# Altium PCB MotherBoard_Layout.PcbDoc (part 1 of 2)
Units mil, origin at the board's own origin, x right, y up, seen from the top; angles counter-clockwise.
Board outline 5200 x 4470 mil, 4 copper layers (Top Layer, Int1 (GND), Int2 (PWR), Bottom Layer), stack 53.912 mil thick; 91 components, 57 nets, 316 pads, 326 vias.
Unrouted connection lines stored in the file: 3.
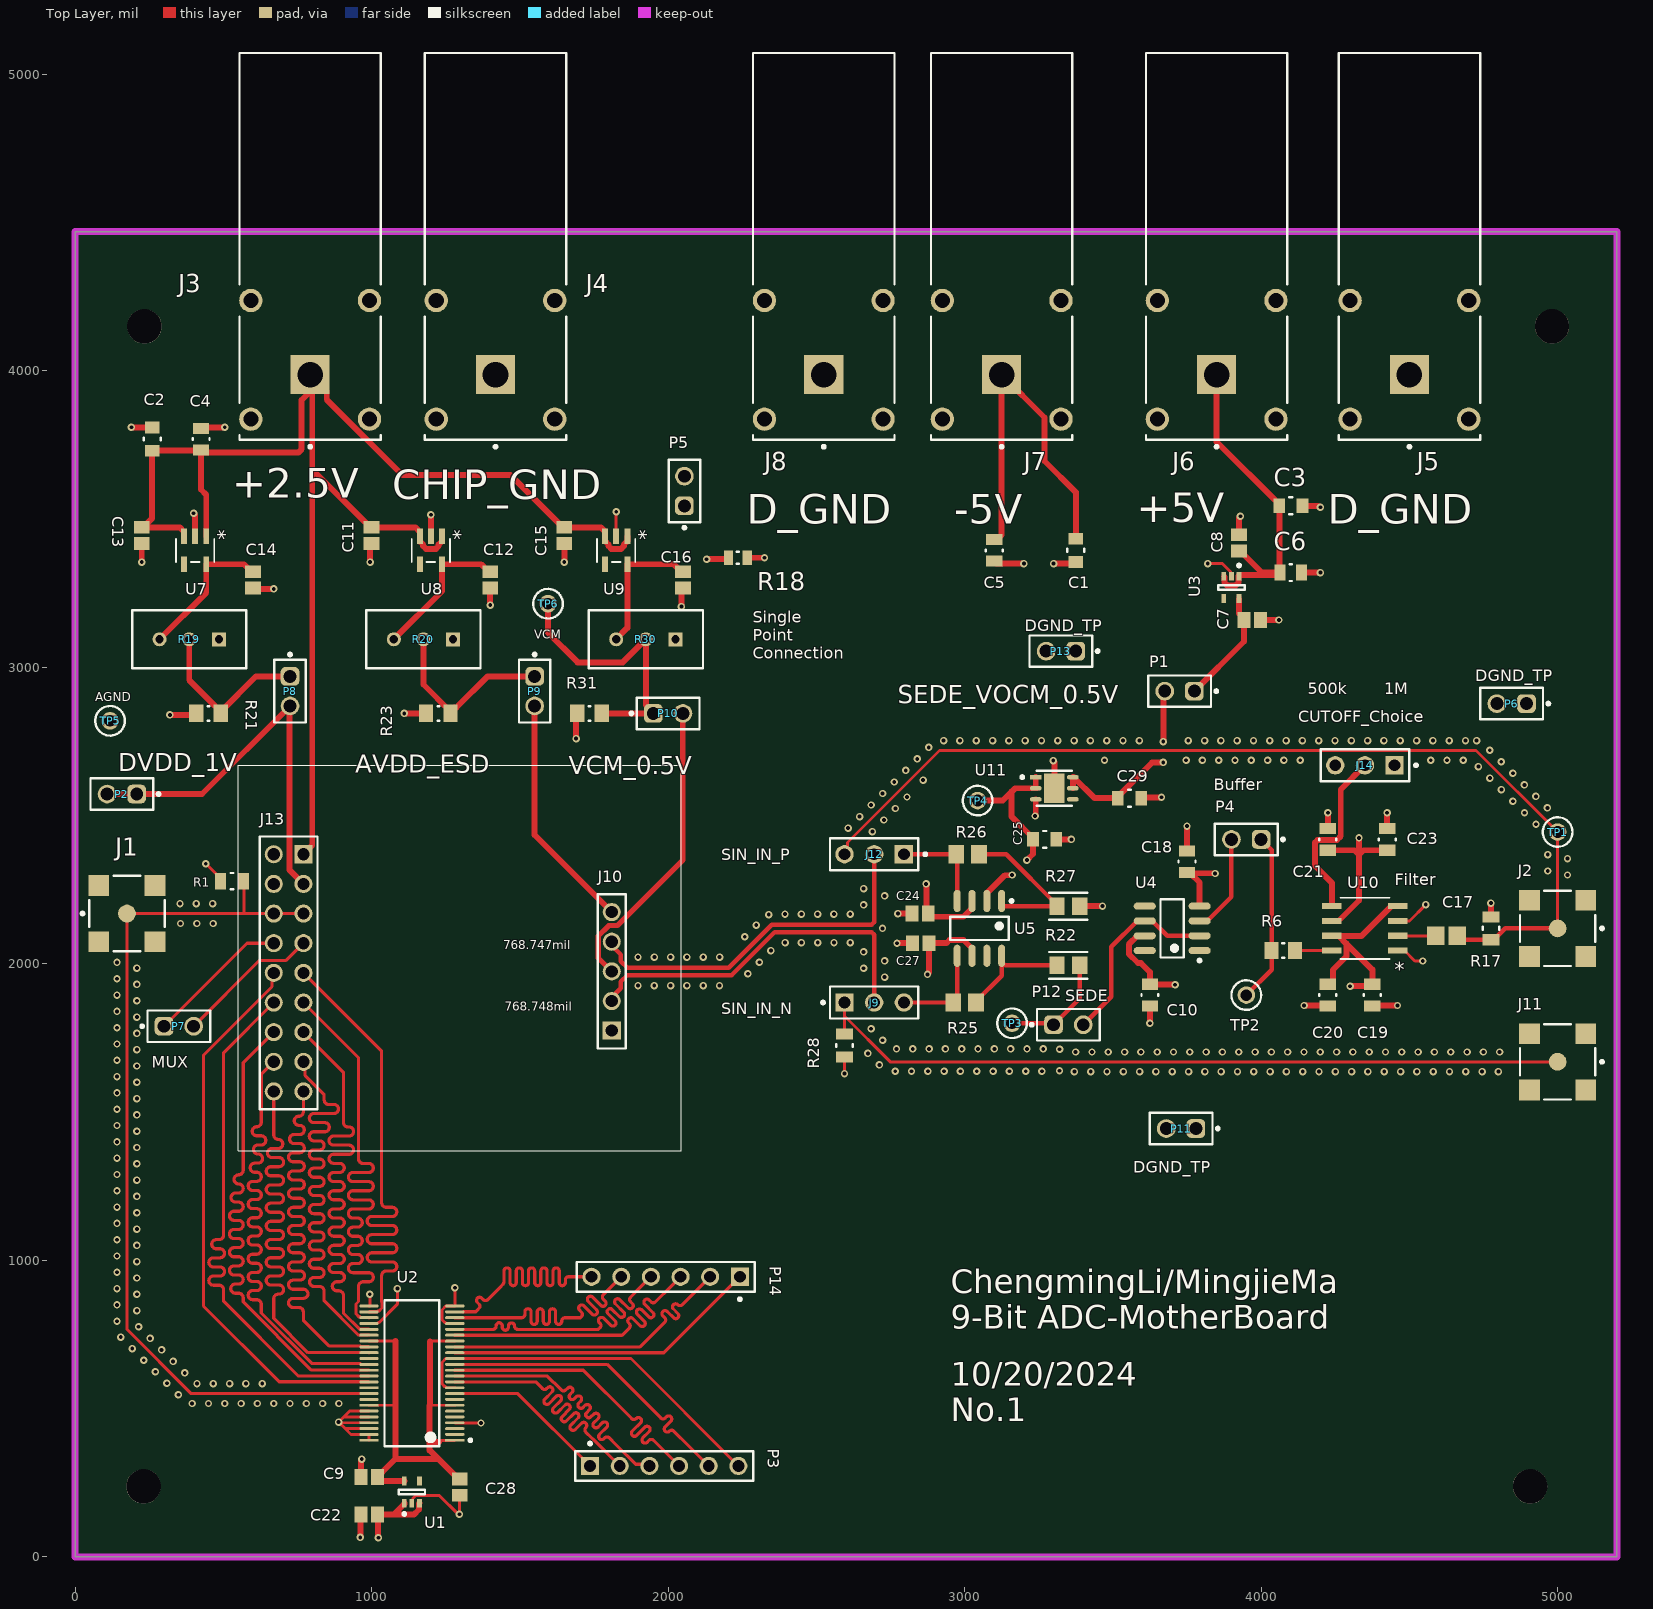
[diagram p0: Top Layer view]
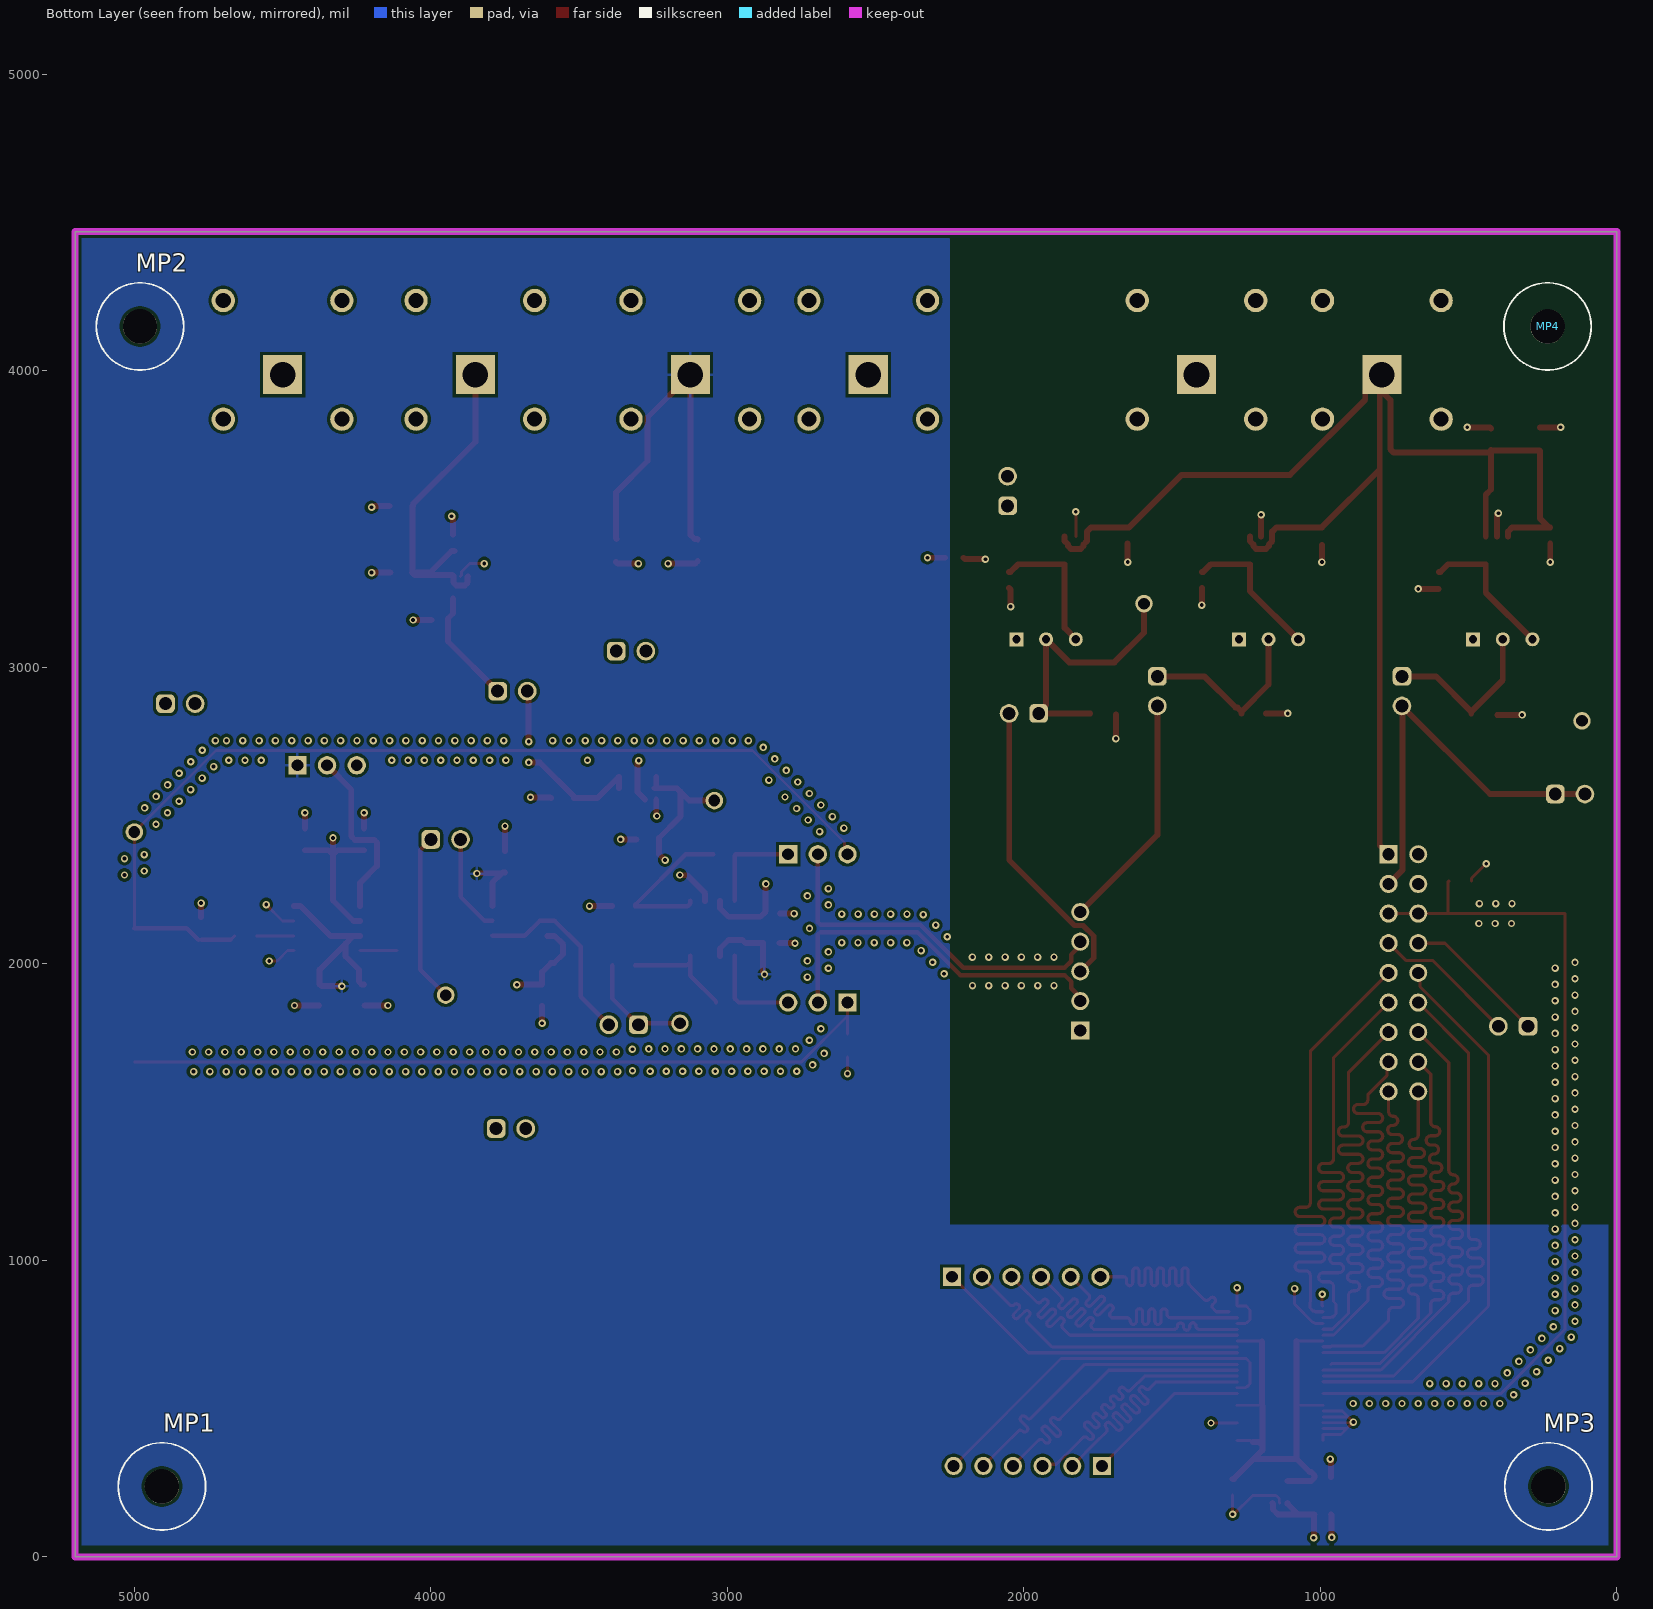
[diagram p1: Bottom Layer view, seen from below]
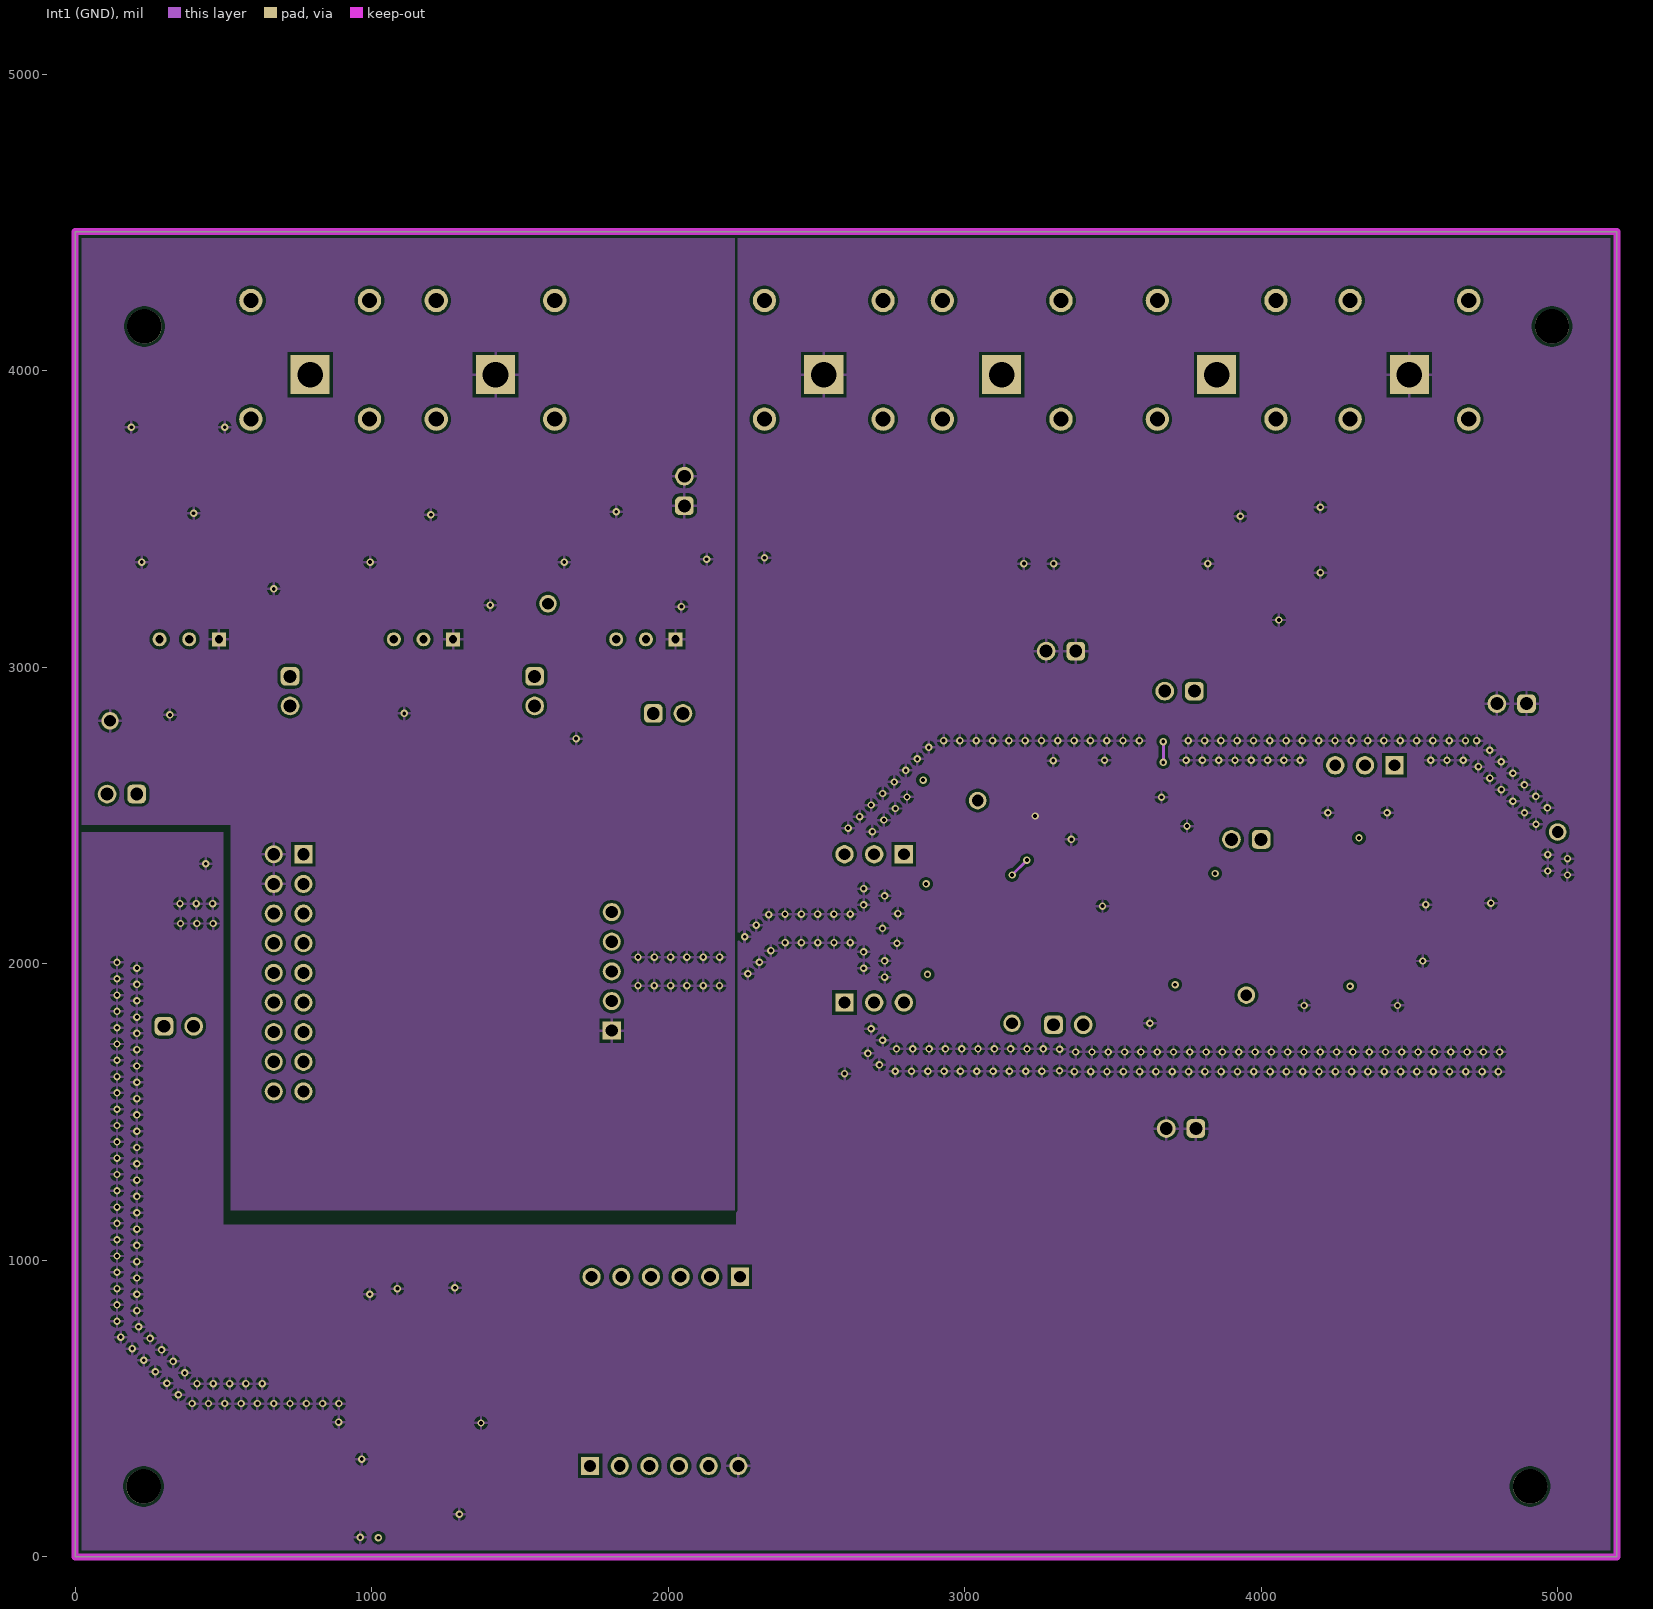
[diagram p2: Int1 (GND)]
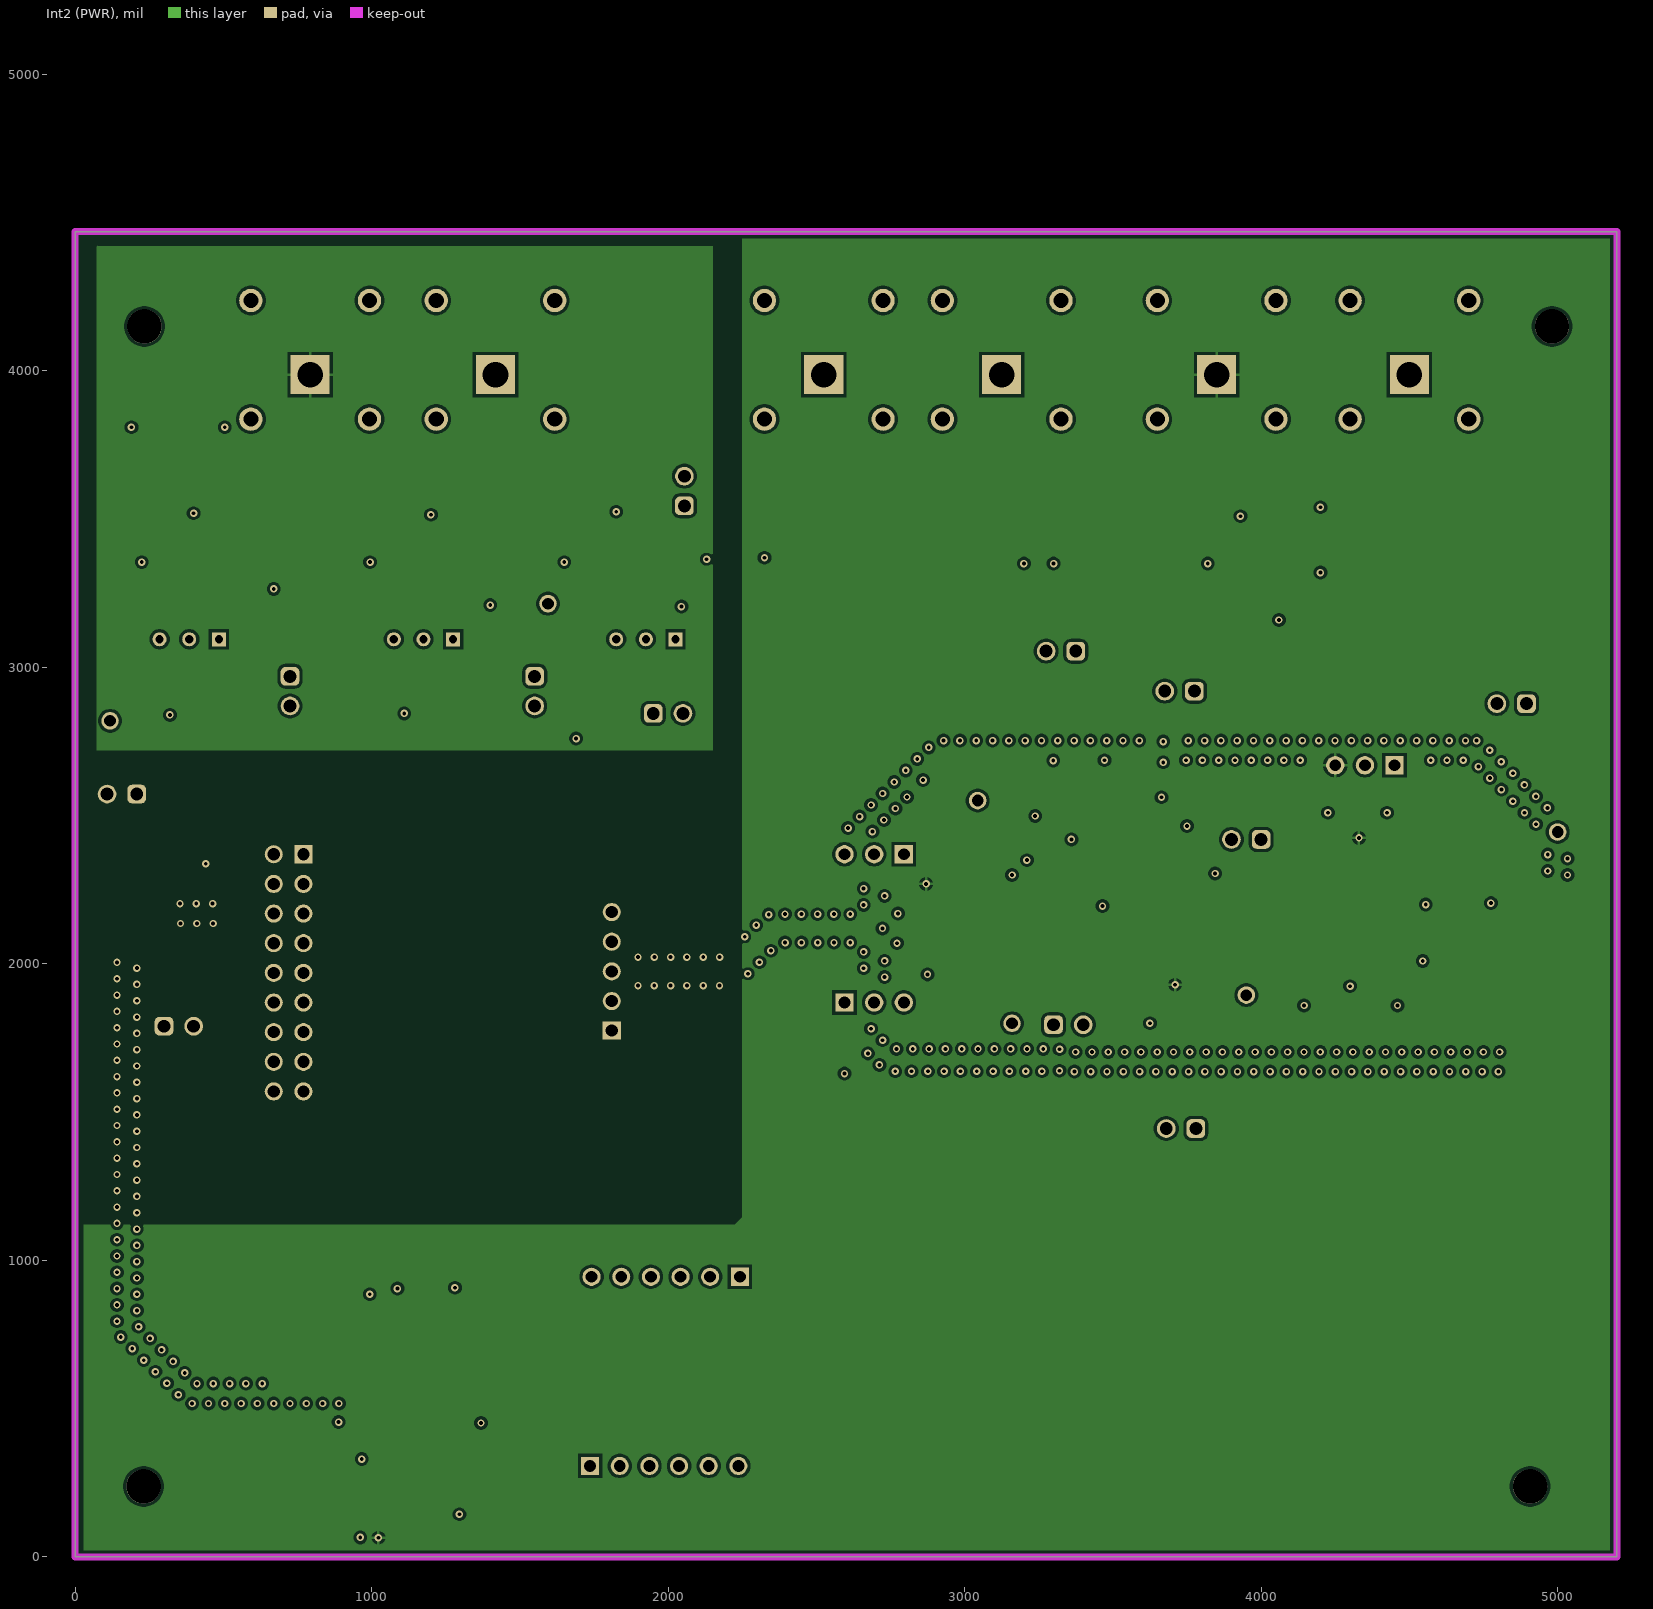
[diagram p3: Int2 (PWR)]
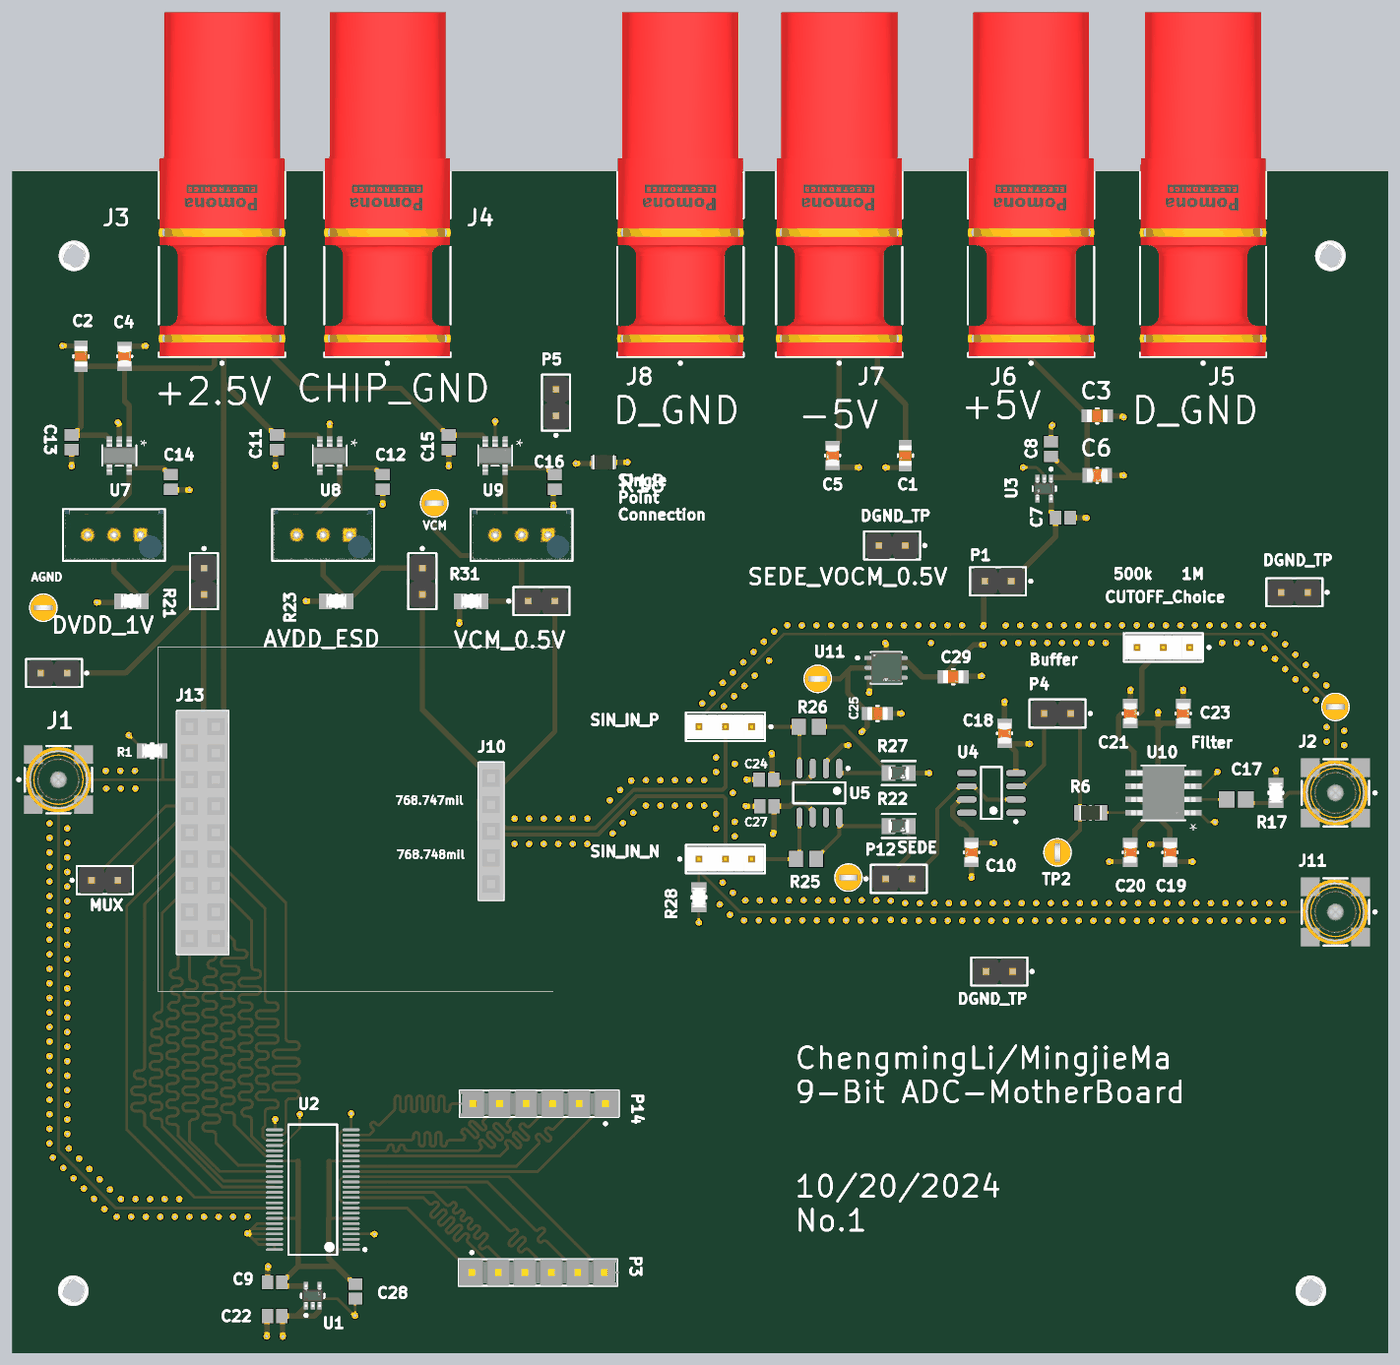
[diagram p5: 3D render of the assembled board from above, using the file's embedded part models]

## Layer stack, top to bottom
Top Solder: solder mask 1, SM-001, Dk 4
Top Layer: signal copper 1.378
Dielectric 1: prepreg 5.1, PP-017, Dk 4.3
Dielectric 2: prepreg 5.1, PP-017, Dk 4.3
Int1 (GND): signal copper 1.378
Dielectric 3: core 28, Core-039, Dk 4.8
Int2 (PWR): signal copper 1.378
Dielectric 4: prepreg 5.1, PP-017, Dk 4.3
Dielectric 5: prepreg 5.1, PP-017, Dk 4.3
Bottom Layer: signal copper 1.378
Bottom Solder: solder mask 1, SM-001, Dk 4

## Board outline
0,0 5200,0 5200,4470 0,4470

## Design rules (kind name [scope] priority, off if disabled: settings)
BoardOutlineClearance [All] p1: gap=12 ignorepadtopadclearanceinfootprint=FALSE except(0: Arc-SplitContinuation Track-SplitContinuation SMDPad-SplitContinuation THPad-SplitContinuation Via-SplitContinuation Fill-SplitContinuation Poly-SplitContinuation Region-SplitContinuation Text-SplitContinuation)
Clearance [All] p1: gap=6 ignorepadtopadclearanceinfootprint=TRUE except(10: Arc-Fill Arc-Poly Arc-Region Track-Fill Track-Poly Track-Region SMDPad-Fill SMDPad-Poly SMDPad-Region THPad-Fill THPad-Poly THPad-Region Via-Fill Via-Poly Via-Region Fill-Fill Fill-Poly Fill-Region Poly-Poly Poly-Region Region-Region)
DiffPairsRouting [All] p1: maxlimit=10 minlimit=10 mostfreqgap=10 toplayer_minwidth=15 toplayer_maxwidth=15 toplayer_prefwidth=15 midlayer1_minwidth=15 midlayer1_maxwidth=15 midlayer1_prefwidth=15 midlayer2_minwidth=15 midlayer2_maxwidth=15 midlayer2_prefwidth=15 bottomlayer_minwidth=15 bottomlayer_maxwidth=15 bottomlayer_prefwidth=15 maxuncoupledlength=500
MatchedLengths BufferOUT_Match [InNetClass('Buffer_OUT')] p1: tolerance=10 checknetsindiffpair=FALSE checkdiffpairvsdiffpair=TRUE checkxsignals=TRUE checkothers=TRUE
MatchedLengths Code_Equal [InNetClass('Code')] p2: tolerance=10 checknetsindiffpair=FALSE checkdiffpairvsdiffpair=TRUE checkxsignals=TRUE checkothers=TRUE
NetAntennae [All] p1 off: netantennaetolerance=0
PlaneClearance [All] p1: clearance=10
PlaneConnect [All] p1: planeconnectstyle=Direct reliefexpansion=20 reliefentries=4 reliefconductorwidth=10 reliefairgap=10
PolygonConnect [All] p1: thpad.connectstyle=Relief thpad.reliefconductorwidth=10 thpad.reliefentries=4 thpad.polygonreliefangle="90 Angle" thpad.airgapwidth=10 smdpad.connectstyle=Direct smdpad.reliefconductorwidth=10 smdpad.reliefentries=4 smdpad.polygonreliefangle="90 Angle" smdpad.airgapwidth=10 via.connectstyle=Relief via.reliefconductorwidth=10 via.reliefentries=4 via.polygonreliefangle="90 Angle" via.airgapwidth=10
RoutingVias [All] p1: holewidth=13 width=25 viastyle="Through Hole" minholewidth=13 minwidth=25 maxholewidth=60 maxwidth=80
SolderMaskExpansion [All] p1: expansion=4 istentingtop=FALSE
UnRoutedNet [All] p1: checkbadconnections=TRUE
Width Buffer_Equal [InNetClass('Buffer_OUT')] p1: maxlimit=10.7 minlimit=5.77 preferedwidth=10.7 toplayer_minwidth=10.7 midlayer1_maxwidth=5.77 midlayer1_prefwidth=5.77 midlayer2_maxwidth=5.77 midlayer2_prefwidth=5.77 bottomlayer_minwidth=10.7 impedanceprofiledriven=TRUE impedanceprofileid={F1170801-20CE-4A2B-8F3A-71DFC4079B53} impedanceprofilevalue=50.000000 minimp=50.000000 maximp=50.000000 favimp=50.000000
Width Code [InNetClass('Code_IN')] p2: maxlimit=10.7 minlimit=5.77 preferedwidth=10.7 toplayer_minwidth=10.7 midlayer1_maxwidth=5.77 midlayer1_prefwidth=5.77 midlayer2_maxwidth=5.77 midlayer2_prefwidth=5.77 bottomlayer_minwidth=10.7 impedanceprofiledriven=TRUE impedanceprofileid={F1170801-20CE-4A2B-8F3A-71DFC4079B53} impedanceprofilevalue=50.000000 minimp=50.000000 maximp=50.000000 favimp=50.000000
Width CLK_50ohm [InNetClass('CLK')] p3: maxlimit=10.7 minlimit=5.77 preferedwidth=10.7 toplayer_minwidth=10.7 midlayer1_maxwidth=5.77 midlayer1_prefwidth=5.77 midlayer2_maxwidth=5.77 midlayer2_prefwidth=5.77 bottomlayer_minwidth=10.7 impedanceprofiledriven=TRUE impedanceprofileid={F1170801-20CE-4A2B-8F3A-71DFC4079B53} impedanceprofilevalue=50.000000 minimp=50.000000 maximp=50.000000 favimp=50.000000
Width "Schematic Width Constraint_3" [InNet('-5')] p4: maxlimit=100 minlimit=10 preferedwidth=40 toplayer_minwidth=20 midlayer1_maxwidth=10 midlayer1_prefwidth=10 midlayer2_maxwidth=10 midlayer2_prefwidth=10 bottomlayer_minwidth=20 minimp=50.000000 maximp=50.000000 favimp=50.000000
Width "Schematic Width Constraint_2" [InNet('+5')] p5: maxlimit=100 minlimit=10 preferedwidth=20 toplayer_minwidth=20 midlayer1_maxwidth=10 midlayer1_prefwidth=10 midlayer2_maxwidth=10 midlayer2_prefwidth=10 bottomlayer_minwidth=20 minimp=50.000000 maximp=50.000000 favimp=50.000000
Width "Schematic Width Constraint_1" [InNet('VDD_2.5V')] p6: maxlimit=100 minlimit=10 preferedwidth=20 toplayer_minwidth=20 midlayer1_maxwidth=10 midlayer1_prefwidth=10 midlayer2_maxwidth=10 midlayer2_prefwidth=10 bottomlayer_minwidth=20 minimp=50.000000 maximp=50.000000 favimp=50.000000
Width "Schematic Width Constraint" [InNet('SEDE_0.5V')] p7: maxlimit=100 minlimit=10 preferedwidth=20 toplayer_minwidth=20 midlayer1_maxwidth=10 midlayer1_prefwidth=10 midlayer2_maxwidth=10 midlayer2_prefwidth=10 bottomlayer_minwidth=20 minimp=50.000000 maximp=50.000000 favimp=50.000000
Width [All] p8: maxlimit=100 minlimit=10 preferedwidth=10 minimp=50.000000 maximp=50.000000 favimp=50.000000
25 further rules are at their usual default settings.

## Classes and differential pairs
net class Code: Code0 Code1 Code2 Code3 Code4 Code5 Code6 Code7 Code8 EOC
net class Buffer_OUT: Code0_BufferOut Code1_BufferOut Code2_BufferOut Code3_BufferOut Code4_BufferOut Code5_BufferOut Code6_BufferOut Code7_BufferOut Code8_BufferOut EOC_BufferOut
net class INPUT_Signal: V_SIN_IN_N
net class CLK: CLK_IN
differential pair IN_T12: +IN_T12_P -IN_T12_N

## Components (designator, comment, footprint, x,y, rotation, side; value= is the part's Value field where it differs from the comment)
C1 "0805ZD106MAT2A" FP-0805-L_2_01_0_2-W_1_25-MFG 3375,3395 r270 top
C2 "0805ZD106MAT2A" FP-0805-L_2_01_0_2-W_1_25-MFG 260,3770 r90 top
C3 "0805ZD106MAT2A" FP-0805-L_2_01_0_2-W_1_25-MFG 4100,3545 r0 top
C4 "CC0805KRX7R8BB104" FP-CC0805-0_85-MFG 425,3770 r90 top value="100 nF"
C5 "CC0805KRX7R8BB104" FP-CC0805-0_85-MFG 3100,3395 r270 top value="100 nF"
C6 "CC0805KRX7R8BB104" FP-CC0805-0_85-MFG 4100,3320 r0 top value="100 nF"
C7 "0805ZC105KAZ2A" CAPC2013X140X50LL20T25 3970,3160 r180 top
C8 "0805ZC105KAZ2A" CAPC2013X140X50LL20T25 3925,3420 r270 top
C9 "0805ZC105KAZ2A" CAPC2013X140X50LL20T25 992,270 r0 top
C10 "CC0805KRX7R8BB104" FP-CC0805-0_85-MFG 3625,1895 r270 top value="100 nF"
C11 "0805ZC105KAZ2A" CAPC2013X140X50LL20T25 1000,3445 r90 top
C12 "0805ZC105KAZ2A" CAPC2013X140X50LL20T25 1400,3295 r90 top
C13 "0805ZC105KAZ2A" CAPC2013X140X50LL20T25 225,3445 r90 top
C14 "0805ZC105KAZ2A" CAPC2013X140X50LL20T25 600,3295 r90 top
C15 "0805ZC105KAZ2A" CAPC2013X140X50LL20T25 1650,3445 r90 top
C16 "0805ZC105KAZ2A" CAPC2013X140X50LL20T25 2050,3295 r90 top
C17 "VJ0805D561KXBAJ" CAPC2013X145X48ML20T23 4625,2095 r180 top
C18 "CC0805KRX7R8BB104" FP-CC0805-0_85-MFG 3750,2345 r90 top value="100 nF"
C19 "CC0805KRX7R8BB104" FP-CC0805-0_85-MFG 4375,1895 r270 top value="100 nF"
C20 "CC0805KRX7R9BB103" FP-CC0805-0_85-MFG 4225,1895 r270 top value="10 nF"
C21 "CC0805KRX7R9BB103" FP-CC0805-0_85-MFG 4225,2420 r90 top value="10 nF"
C22 "0805ZC105KAZ2A" CAPC2013X140X50LL20T25 992,143 r0 top
C23 "CC0805KRX7R8BB104" FP-CC0805-0_85-MFG 4425,2420 r90 top value="100 nF"
C24 "0805ZC105KAZ2A" CAPC2013X140X50LL20T25 2850,2170 r0 top
C25 "0805ZD106MAT2A" FP-0805-L_2_01_0_2-W_1_25-MFG 3270,2420 r0 top
C27 "0805ZC105KAZ2A" CAPC2013X140X50LL20T25 2852,2070 r0 top
C28 "0805ZC105KAZ2A" CAPC2013X140X50LL20T25 1297,236 r90 top
C29 "0805ZD106MAT2A" FP-0805-L_2_01_0_2-W_1_25-MFG 3556,2559 r0 top
J1 "73251-1350" FP-73251-1350-MFG 175,2170 r0 top
J2 "73251-1350" FP-73251-1350-MFG 5000,2120 r180 top
J3 "73099-2" FP-73099-2-MFG 793,4420 r90 top
J4 "73099-2" FP-73099-2-MFG 1418,4420 r90 top
J5 "73099-2" FP-73099-2-MFG 4500,4420 r90 top
J6 "73099-2" FP-73099-2-MFG 3850,4420 r90 top
J7 "73099-2" FP-73099-2-MFG 3125,4420 r90 top
J8 "73099-2" FP-73099-2-MFG 2525,4420 r90 top
J9 "22-10-2031" FP-22-10-2031-MFG 2695,1870 r0 top
J10 "SSW-105-01-T-S" SMTC-SSW-105-01-X-S 1810,1775 r90 top
J11 "73251-1350" FP-73251-1350-MFG 5000,1670 r180 top
J12 "22-10-2031" FP-22-10-2031-MFG 2695,2370 r180 top
J13 "SSW-109-01-T-D" SMTC-SSW-109-01-X-D 770,2370 r270 top
J14 "22-10-2031" FP-22-10-2031-MFG 4350,2670 r180 top
MP1 "1921B" FP-1921B-MFG 4907,238 r180 bottom
MP2 "1921B" FP-1921B-MFG 4981,4150 r180 bottom
MP3 "1921B" FP-1921B-MFG 231,238 r180 bottom
MP4 "1921B" FP-1921B-MFG 234,4150 r180 bottom
P1 "61300211121" 61300211121 3725,2920 r180 top
P2 "61300211121" 61300211121 158,2573 r180 top
P3 "TSW-106-07-S-S" SMTC-TSW-106-07-S-S_V 1987,307 r0 top
P4 "61300211121" 61300211121 3950,2420 r180 top
P5 "61300211121" 61300211121 2055,3595 r90 top
P6 "61300211121" 61300211121 4845,2878 r180 top
P7 "61300211121" 61300211121 350,1790 r0 top
P8 "61300211121" 61300211121 725,2920 r270 top
P9 "61300211121" 61300211121 1550,2920 r270 top
P10 "61300211121" 61300211121 2000,2845 r0 top
P11 "61300211121" 61300211121 3730,1445 r180 top
P12 "61300211121" 61300211121 3350,1795 r0 top
P13 "61300211121" 61300211121 3325,3055 r180 top
P14 "TSW-106-07-S-S" SMTC-TSW-106-07-S-S_V 1992,945 r180 top
R1 "CRCW080550R0FKTA" FP-D12-CRCW0805-MFG 529,2279 r180 top
R6 "RC0805FR-071KL" RESC2013X60X35ML10T20 4075,2045 r180 top
R17 "CRCW080550R0FKTA" FP-D12-CRCW0805-MFG 4775,2120 r90 top
R18 "RC0805JR-100RL" RESC2013X60X35LL10T20 2235,3370 r0 top
R19 "3296W-1-253LF" FP-3296W-MFG 385,3094.8 r90 top
R20 "3296W-1-253LF" FP-3296W-MFG 1175,3094.8 r90 top
R21 "CRCW080510K0FKEA" FP-CRCW0805-e3-IPC_A 450,2845 r180 top
R22 "CRCW0805100RFKEAHP" FP-CRCW0805-HPe3-IPC_A 3350,1995 r180 top
R23 "CRCW080510K0FKEA" FP-CRCW0805-e3-IPC_A 1225,2845 r180 top
R25 "ERJ-6ENF2000V" RESC2013X70X40ML20T20 3000,1870 r180 top value=200ohm
R26 "ERJ-6ENF2000V" RESC2013X70X40ML20T20 3010,2370 r180 top value=200ohm
R27 "CRCW0805100RFKEAHP" FP-CRCW0805-HPe3-IPC_A 3350,2195 r180 top
R28 "CRCW080550R0FKTA" FP-D12-CRCW0805-MFG 2595,1725 r90 top
R30 "3296W-1-253LF" FP-3296W-MFG 1925,3094.8 r90 top
R31 "CRCW080510K0FKEA" FP-CRCW0805-e3-IPC_A 1735,2845 r180 top
TP1 "5003" KSTN-5003 5000,2445 r0 top
TP2 "5003" KSTN-5003 3950,1895 r270 top
TP3 "5003" KSTN-5003 3160,1800 r0 top
TP4 "5003" KSTN-5003 3044,2551 r0 top
TP5 "5003" KSTN-5003 118,2820 r0 top
TP6 "5003" KSTN-5003 1595,3215 r0 top
U1 "MIC5365-2.5YC5-TR" FP-SC70-5LD-PL-1-MFG 1136,219 r90 top
U2 "SN74LVC16244ADGGR" FP-DGG0048A-IPC_B 1136,620 r180 top
U3 "MIC5365-2.5YC5-TR" FP-SC70-5LD-PL-1-MFG 3900,3270 r270 top
U4 "LT1360CS8#PBF" LT-S8-8_L 3700,2120 r180 top
U5 "ADA4940-1ARZ" ADI-R-8_L 3050,2120 r270 top
U7 "TPL503115-S5TR" SOT23-5-A_TPK 405,3395 r270 top
U8 "TPL503115-S5TR" SOT23-5-A_TPK 1200,3395 r270 top
U9 "TPL503115-S5TR" SOT23-5-A_TPK 1825,3395 r270 top
U10 "LTC1560-1CS8PBF" SO-8_S_LIT-M 4350,2120 r180 top
U11 "LD39200PUR" FP-DFN6-7946637-IPC_A 3302.86,2592.6 r0 top

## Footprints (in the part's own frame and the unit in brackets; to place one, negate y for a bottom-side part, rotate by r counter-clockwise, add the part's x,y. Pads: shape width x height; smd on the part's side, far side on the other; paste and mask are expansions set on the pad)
61300211121 [mm] "Pin Header, pitch 2.54 mm, THT, Vertical, single row, 2p"
  rrect50% 1.6x1.6 hole 1.1: 1(-1.27,0)
  round 1.6 hole 1.1: 2(1.27,0)
  silkscreen extent -3.26,-1.35 2.69,1.35, body extent -2.54,-1.27 2.54,1.27, height 8.57
ADI-R-8_L [mm] "SOIC, 8-Leads, Body 4.9x3.9mm, Pitch 1.27mm, IPC High Density"
  oval 1.9x0.6 smd: 1(-2.35,1.905) 2(-2.35,0.635) 3(-2.35,-0.635) 4(-2.35,-1.905) 5(2.35,-1.905) 6(2.35,-0.635) 7(2.35,0.635) 8(2.35,1.905)
  silkscreen extent -2.47,-2.5 1,2.88, body extent -2,-2.5 2,2.5, height 1.75
CAPC2013X140X50LL20T25 [mm] "Chip Capacitor, 2-Leads, Body 2.00x1.25mm, IPC High Density"
  rect 1.1x1.35 smd: 1(-0.7,0) 2(0.7,0)
  body extent -1.1,-0.72 1.1,0.72, height 1.4
CAPC2013X145X48ML20T23 [mm] "Chip Capacitor, 2-Leads, Body 2.00x1.25mm, IPC Low Density"
  rect 1.5x1.55 smd: 1(-0.925,0) 2(0.925,0)
  body extent -1.1,-0.72 1.1,0.72, height 1.45
FP-22-10-2031-MFG [mm]
  rect 1.57x1.57 hole 1.02 paste-1000 mask+0: 1(-2.54,0)
  round 1.57 hole 1.02 paste-1000 mask+0: 2(0,0) 3(2.54,0)
  silkscreen extent -4.5,-1.37 3.78,1.37, body extent -3.89,-1.47 3.89,1.47, height 0.25
FP-0805-L_2_01_0_2-W_1_25-MFG [mm]
  rect 1x1.25 smd paste+0 mask+0: 1(-1,0) 2(1,0)
  silkscreen extent -0.13,-0.72 0.13,0.72, body extent -1.6,-0.82 1.6,0.82, height 0.25
FP-1921B-MFG [mil]
  round 116 hole 116 unplated paste-39370.1 mask+0: ""(0,0)
  silkscreen extent -147,-147 147,147, body extent -144,-125 144,125, height 505
FP-3296W-MFG [mm]
  rect 1.2x1.2 hole 0.7 paste-1000 mask+0: 1(0.005,-2.54)
  round 1.2 hole 0.7 paste-1000 mask+0: 2(0.005,0) 3(0.005,2.54)
  silkscreen extent -2.48,-4.89 2.48,4.89, body extent -2.58,-4.99 2.58,4.99, height 0.25
FP-73099-2-MFG [mm]
  rect 3.35x3.35 hole 2.2 paste-1000 mask+0: 1(-10.986,0)
  round 2 hole 1.3 paste-1000 mask+0: 2(-14.795,5.08) 3(-4.635,5.08) 4(-14.795,-5.08) 5(-4.635,-5.08)
  silkscreen extent -17.29,-6.06 16.56,6.06, body extent -16.66,-6.18 16.66,6.18, height 0.25
FP-73251-1350-MFG [mil]
  round 60 smd paste+0 mask+0: 1(0,0)
  rect 70x70 smd paste+0 mask+0: 2(-95,95) 3(95,95) 4(-95,-95) 5(95,-95)
  silkscreen extent -155,-127 127,127, body extent -134,-134 134,134, height 10
FP-CC0805-0_85-MFG [mm]
  rect 0.95x1.4 smd paste+0 mask+0: 1(-0.925,0) 2(0.925,0)
  silkscreen extent -0.08,-0.72 0.08,0.72, body extent -1.6,-1.05 1.6,1.05, height 0.25
FP-CRCW0805-e3-IPC_A [mil]
  rect 47.5x59.38 smd paste+0 mask+0: 1(-41.37,0) 2(41.37,0)
  silkscreen extent -3,-25 3,25, body extent -85,-49 85,49, height 10
FP-CRCW0805-HPe3-IPC_A [mil]
  rect 51.42x59.38 smd paste+0 mask+0: 1(-38.43,0) 2(38.43,0)
  silkscreen extent -64,-45 64,45, body extent -84,-49 84,49, height 10
FP-D12-CRCW0805-MFG [mm]
  rect 0.95x1.45 smd paste+0 mask+0: 1(-0.975,0) 2(0.975,0)
  silkscreen extent -0.13,-0.7 0.13,0.7, body extent -1.55,-0.82 1.55,0.82, height 0.25
FP-DFN6-7946637-IPC_A [mm]
  rect 1.01x0.381 smd paste+0 mask+0: 1(-1.597,0.95)
  rrect100% 1.01x0.381 smd paste+0 mask+0: 2(-1.597,0) 3(-1.597,-0.95) 4(1.578,-0.95) 5(1.578,0) 6(1.578,0.95)
  rect 1.75x2.5 smd paste-1000 mask+0: 7(0,0)
  silkscreen extent -2.88,-1.5 1.5,1.5, body extent -2.46,-2 2.46,2, height 0.25
FP-DGG0048A-IPC_B [mm]
  rect 1.655x0.252 smd paste+0 mask+0: 1(-3.675,5.75)
  rrect100% 1.655x0.252 smd paste+0 mask+0: 2(-3.675,5.25) 3(-3.675,4.75) 4(-3.675,4.25) 5(-3.675,3.75) 6(-3.675,3.25) 7(-3.675,2.75) 8(-3.675,2.25) 9(-3.675,1.75) 10(-3.675,1.25) 11(-3.675,0.75) 12(-3.675,0.25) 13(-3.675,-0.25) 14(-3.675,-0.75) 15(-3.675,-1.25) 16(-3.675,-1.75) 17(-3.675,-2.25) 18(-3.675,-2.75) 19(-3.675,-3.25) 20(-3.675,-3.75) 21(-3.675,-4.25) 22(-3.675,-4.75) 23(-3.675,-5.25) 24(-3.675,-5.75) 25(3.675,-5.75) 26(3.675,-5.25) 27(3.675,-4.75) 28(3.675,-4.25) 29(3.675,-3.75) 30(3.675,-3.25) 31(3.675,-2.75) 32(3.675,-2.25) 33(3.675,-1.75) 34(3.675,-1.25) 35(3.675,-0.75) 36(3.675,-0.25) 37(3.675,0.25) 38(3.675,0.75) 39(3.675,1.25) 40(3.675,1.75) 41(3.675,2.25) 42(3.675,2.75) 43(3.675,3.25) 44(3.675,3.75) 45(3.675,4.25) 46(3.675,4.75) 47(3.675,5.25) 48(3.675,5.75)
  silkscreen extent -5.13,-6.25 2.35,6.25
FP-SC70-5LD-PL-1-MFG [mm]
  rect 0.75x0.4 smd paste+0 mask+0: 1(-0.95,0.65) 2(-0.95,0) 3(-0.95,-0.65) 4(0.95,-0.65) 5(0.95,0.65)
  silkscreen extent -2,-1.12 0.2,1.12, body extent -1.43,-1.22 1.43,1.22, height 0.25
KSTN-5003 [mm] "Test Point, Through Hole, Dia 2.54mm"
  round 1.5 hole 1: 1(0,0)
  silkscreen extent -1.27,-1.27 1.27,1.27, body extent -1.27,-1.27 1.27,1.27, height 4.57
LT-S8-8_L [mm] "SOIC, 8-Leads, Body 4.9x3.9mm, Pitch 1.27mm, IPC High Density"
  oval 1.9x0.6 smd: 1(-2.35,1.905) 2(-2.35,0.635) 3(-2.35,-0.635) 4(-2.35,-1.905) 5(2.35,-1.905) 6(2.35,-0.635) 7(2.35,0.635) 8(2.35,1.905)
  silkscreen extent -2.48,-2.5 1,2.88, body extent -2,-2.5 2,2.5, height 1.76
RESC2013X60X35LL10T20 [mm] "Chip Resistor, 2-Leads, Body 2.1x1.35mm, IPC High Density"
  rect 0.8x1.25 smd: 1(-0.8,0) 2(0.8,0)
  silkscreen extent -0.1,-0.53 0.1,0.53, body extent -1.05,-0.67 1.05,0.68, height 0.6
RESC2013X60X35ML10T20 [mm] "Chip Resistor, 2-Leads, Body 2.1x1.35mm, IPC Low Density"
  rect 1.2x1.45 smd: 1(-1,0) 2(1,0)
  silkscreen extent -0.1,-0.63 0.1,0.63, body extent -1.05,-0.68 1.05,0.67, height 0.6
RESC2013X70X40ML20T20 [mm] "Chip Resistor, 2-Leads, Body 2.00x1.25mm, IPC Low Density"
  rect 1.35x1.55 smd: 1(-0.975,0) 2(0.975,0)
  body extent -1.1,-0.72 1.1,0.72, height 0.7
SMTC-SSW-105-01-X-S [mm] "SQ Post Socket, 1x5 Pins, Vertical, 2.54mm Pitch, Female"
  rect 1.55x1.55 hole 1.04: 1(0,0)
  round 1.55 hole 1.04: 2(2.54,0) 3(5.08,0) 4(7.62,0) 5(10.16,0)
  silkscreen extent -1.53,-1.2 11.69,1.2, body extent -1.52,-1.21 11.68,1.21, height 8.51
SMTC-SSW-109-01-X-D [mm] "SQ Post Socket, 2x9 Pins, Vertical, 2.54mm Pitch, Female"
  rect 1.55x1.55 hole 1.04: 1(0,0)
  round 1.55 hole 1.04: 2(0,-2.54) 3(2.54,0) 4(2.54,-2.54) 5(5.08,0) 6(5.08,-2.54) 7(7.62,0) 8(7.62,-2.54) 9(10.16,0) 10(10.16,-2.54) 11(12.7,0) 12(12.7,-2.54) 13(15.24,0) 14(15.24,-2.54) 15(17.78,0) 16(17.78,-2.54) 17(20.32,0) 18(20.32,-2.54)
  silkscreen extent -1.53,-3.74 21.85,1.2, body extent -1.52,-3.75 21.84,1.21, height 8.51
SMTC-TSW-106-07-S-S_V [mm] "Header, 6-Leads, Body 15.24x2.54mm, Pitch 2.54mm"
  rect 1.55x1.55 hole 1.02: 1(-6.35,0)
  round 1.55 hole 1.02: 2(-3.81,0) 3(-1.27,0) 4(1.27,0) 5(3.81,0) 6(6.35,0)
  silkscreen extent -7.62,-1.27 7.62,2.04, body extent -7.62,-1.27 7.75,1.27, height 8.38
SO-8_S_LIT-M [mil]
  rect 65.5x21 smd paste+0 mask+0: 1(-111.25,75) 2(-111.25,25) 3(-111.25,-25) 4(-111.25,-75) 5(111.25,-75) 6(111.25,-25) 7(111.25,25) 8(111.25,75)
  silkscreen extent -84,-104 84,104, body extent -122,-99 122,99, height 69
SOT23-5-A_TPK [mil]
  rect 52x20 smd paste+0 mask+0: 1(-47,37.4) 2(-47,0) 3(-47,-37.4) 4(47,-37.4) 5(47,37.4)
  silkscreen extent -39,-65 39,65, body extent -59,-59 59,59, height 49

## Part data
C1 C2 C3 C25 C29: library part CMP-2007-04682-2, "General Purpose Ceramic Capacitor, 0805, 10uF, 20%, X5R, 15%, 10V", Capacitance=10uF, Case Code (Imperial)=0805, Case Code (Metric)=2012, Dielectric=X5R, Dielectric Material=Ceramic, Insulation Resistance=10GR, Max Operating Temperature=85°C, Min Operating Temperature=-55°C, Package Quantity=3000, Tolerance=20%, Voltage=10V
C4 C5 C6 C10 C18 C19 C23: library part CMP-1036-04410-2, "CAP CER 0.1UF 25V X7R 0805", Capacitance="100 nF", Manufacturer=Yageo, Package=CC0805-0.85, Temperature="-30°C to +85°C", Temperature Characteristic=X7R, Temperature Range High=+85°C, Temperature Range Low=-30°C, Tolerance=0.1, Voltage Rating="25 V"
C7 C8 C9 C11 C12 C13 C14 C15 C16 C22 C24 C27 C28: library part CMP-2007-04674-1, Manufacturer="AVX Interconnect / Elco"
C17: library part CMP-2007-03149-1, Manufacturer=Vitramon
C20 C21: library part CMP-1036-03842-3, "CAP CER 10000PF 50V X7R 0805", Capacitance="10 nF", Manufacturer=Yageo, Package=CC0805-0.85, Temperature="-30°C to +85°C", Temperature Characteristic=X7R, Temperature Range High=+85°C, Temperature Range Low=-30°C, Tolerance=0.1, Voltage Rating="50 V"
J1 J2 J11: library part CMP-04764-000006-1, "CONN SMA JACK STR 50 OHM SMD", Frequency=18GHz, Manufacturer=Molex, Temperature="-65°C to +165°C", Temperature Range High=+165°C, Temperature Range Low=-65°C, Voltage Rating=500V
J3 J4 J5 J6 J7 J8: library part CMP-73906-000005-1, "R/A 4MM MOUNTG SAFE JACK/PCB RED"
J9 J12 J14: library part CMP-04776-000653-1, "CONN HEADER VERT 3POS 2.54MM", Color=White, Contact Resistance=10mR, Current Rating=4A, Flammability Rating="UL94 V-0", Insulation Resistance=50GR, Max Operating Temperature=75°C, Max Voltage Rating (AC)=250V, Min Operating Temperature=0°C, Package Quantity=2000
J10: library part CMP-1023-00345-1, "SQ Post Socket, Through-hole, Vertical, -55 to 105 degC, 2.54mm Pitch, 5-Pin, Female, RoHS", Manufacturer=Samtec, Temperature Range="-55 to 105 degC"
J13: library part CMP-1023-00387-1, "SQ Post Socket, Through-hole, Vertical, -55 to 105 degC, 2.54mm Pitch, 18-Pin, Female, RoHS", Manufacturer=Samtec, Temperature Range="-55 to 105 degC"
MP1 MP2 MP3 MP4: library part CMP-00214-00374361-1, "1921B Standoff, 1/4 Hex, Female, Threaded 4-40, Length .500, Stainless Steel", Color=Natural
P1 P2 P4 P5 P6 P7 P8 P9 P10 P11 P12 P13: library part CMP-1712-00002-6, Color=Black, Contact Resistance=20mΩ, Current Rating=3A, Max Operating Temperature=125°C, Min Operating Temperature=-40°C, Operating Supply Voltage=250V
P3 P14: library part CMP-1681-00007-2, "Male Header, Pitch 2.54 mm, 1 x 6 Position, Height 8.38 mm, Tail Length 2.54 mm, -55 to 125 degC, RoHS, Bulk", Colour=Black, Manufacturer=Samtec, Max Operating Temperature="125 degC", Min Operating Temperature="-55 degC", Package Quantity=1
R1 R17 R28: library part CMP-00030-21390498-1, "CRCW080550R0FKTA Res Thick Film 0805 50 Ohm 1% 0.125W(1/8W) ±100ppm/C Pad SMD Automotive T/R", Case Code (Imperial)=0805, Case Code (Metric)=2012, Max Operating Temperature=155°C, Min Operating Temperature=-55°C, Power Rating=125mW, Resistance=50Ω, Temperature Coefficient=100ppm/°C, Tolerance=1%, Voltage Rating=150V
R6: library part CMP-2100-03671-1, "Chip Resistor, 1 KOhm, +/- 1%, 125 mW, -55 to 155 degC, 0805 (2012 Metric), RoHS, Tape and Reel", Case Code (Imperial)=0805, Case Code (Metric)=2012, Manufacturer=Yageo, Max Operating Temperature=155degC, Max Power Dissipation=125mW, Min Operating Temperature=-55degC, Package Description="2-Pin Surface Mounted Device, Body 2 x 1.25 mm", Package Quantity=1, Resistance=1KOhm, Temperature Coefficient=100ppm/degreesC, Tolerance=1%, Voltage Rating=150V
R18: library part CMP-2000-06963-1, "Chip Resistor, 0 Ohm, +/- 5%, 125 mW, -55 to 155 degC, 0805 (2012 Metric), RoHS, Tape and Reel", Case Style=Molded, Manufacturer=Yageo, Operating Temp Range=-55Cto155C, Package / Case=0805, Package Description="2-Pin Surface Mounted Device, Body 2 x 1.25 mm", Power Rating(s)=NotRequiredW, Temperature Coefficient=NotRequired
R19 R20 R30: library part CMP-07234-000034-1, "TRIMMER 25K OHM 0.5W PC PIN TOP", Color=Blue, Max Operating Temperature=125°C, Max Power Dissipation=500mW, Min Operating Temperature=-55°C, Package Quantity=50, Resistance=25kR, Resistance Tolerance=10%, Resistor Type=Cermet, Temperature Coefficient=100ppm/°C, Voltage Rating (DC)=300V
R21 R23 R31: library part CMP-2001-04908-2, "RES Thick Film, 10kΩ, 1%, 0.125W, 100ppm/°C, 0805", Case Code (Imperial)=0805, Case Code (Metric)=2012, Max Operating Temperature=155°C, Min Operating Temperature=-55°C, Package Quantity=5000, Power Rating=125mW, Resistance=10kR, Temperature Coefficient=100ppm/°C, Tolerance=1%, Voltage Rating=150V
R22 R27: library part CMP-02407-011702-1, "RES Thick Film, 100Ω, 1%, 0.5W, 100ppm/°C, 0805", Case Code (Imperial)=0805, Case Code (Metric)=2012, Max Operating Temperature=155°C, Max Power Dissipation=500mW, Min Operating Temperature=-55°C, Package Quantity=5000, Power Rating=330mW, Resistance=100R, Resistance Tolerance=1%, Resistor Type="Thick Film", Temperature Coefficient=100ppm/°C, Voltage Rating=150V
R25 R26: library part CMP-2001-00025-1, Manufacturer=Panasonic
TP1 TP2 TP3 TP4 TP5 TP6: library part CMP-1672-00009-1, "Test Point, Orange, 1-Pin THD, RoHS", Forward Current="3 A", Forward Voltage="1.08 V", Max Operating Temperature="150 degC", Max Surge Current="80 A", Min Operating Temperature="-65 degC", Package Quantity=500, Peak Reverse Current="600 uA"
U1 U3: library part CMP-06324-000051-1, "IC REG LINEAR 2.5V 150MA SC70-5", Case/Package=SC, Dropout Voltage=180mV, Max Input Voltage=5.5V, Max Operating Temperature=125°C, Max Output Current=150mA, Min Current Limit=200mA, Min Input Voltage=2.5V, Min Operating Temperature=-40°C, Output Voltage Accuracy=2%, Package Quantity=1, Power Supply Rejection Ratio (PSRR)=80dB, Quiescent Current=39uA
U2: library part CMP-0440-00473-4, "IC BUF NON-INVERT 3.6V 48TSSOP", Case/Package=TSSOP, High Level Output Current=-24mA, Low Level Output Current=24mA, Max Operating Temperature=125°C, Max Supply Voltage=3.6V, Min Operating Temperature=-40°C, Min Supply Voltage=1.65V, Package Quantity=2000, Quiescent Current=20uA
U4: library part CMP-0359-02753-2, "Single Channel, High Speed Precision Operational Amplifier, 50 MHz Typical GBW, 800 V/us Typical SR, 3 to 36 V, 8-Pin SOIC (S8-8), Commerical, Pb-Free", Linear Technology Part Number=LT1360, Manufacturer="Linear Technology"
U5: library part CMP-1331-00005-2, "Ultralow Power, Low Distortion Fully Differential ADC Driver, 3 to 6 V, -40 to 125 degC, 8-Pin SOIC_N (R-8), RoHS, Tube"
U7 U8 U9: "No Description Available", Mfr_Name=3Peak
U10: "No Description Available", Mfr_Name="Analog Devices Inc"
U11: library part CMP-12153-000004-1, "IC REG LINEAR POS ADJ 2A 6DFN", Dropout Voltage=135mV, Manufacturer=STMicroelectronics, Max Junction Temp=+125°C, Max Supply Voltage=6V, Min Supply Voltage=1.25V, Nominal Supply Current=100-1000uA, Output Current=2A, Package=DFN6-7946637, Temperature="-40°C to +125°C", Temperature Range Low=-40°C

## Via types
v1: diameter 25, hole 13, Top Layer to Bottom Layer, 326 vias

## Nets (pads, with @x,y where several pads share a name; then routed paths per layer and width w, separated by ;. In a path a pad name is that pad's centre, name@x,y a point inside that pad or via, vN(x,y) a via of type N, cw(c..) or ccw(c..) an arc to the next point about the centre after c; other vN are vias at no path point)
2.5V_Buffer: C9.2 C28.2 U1.5 U2.1 U2.7 U2.18 U2.31 U2.42 | length 1675.2
  Top Layer w10: U2.42@991.3,511.73 1079.29,511.73 1080.56,513 ; U2.31@991.3,728.27 1079.73,728.27 1080,728 ; 1197,727 1198.27,728.27 U2.18@1280.7,728.27 ; 1197.19,511.73 U2.7@1280.7,511.73 ; 1228,388 1233.59,393.59 U2.1@1280.7,393.62
  Top Layer w20: 1080,728 1080.56,727.44 1080.56,513 1080.56,331 ; U1.5@1110.41,256.4 1031.21,256.4 1019.56,268.06 C9.2@1019.56,270 1019.56,274.92 1031.21,286.57 1036.13,286.57 1080.56,331 ; 1197,727 1197.19,726.81 1197.19,511.73 1195.92,510.46 1195.92,376.28 ; 1228,388 1207.64,388 1195.92,376.28 ; C28.2@1297,263.56 1292.08,263.56 1224.64,331 ; 1080.56,331 1224.64,331 ; 1195.92,376.28 1195.92,359.72 1224.64,331
+5: C3.1 C6.1 C8.2 C10.1 C21.1 C22.2 C23.1 C24.2 J6.1 J14.3 U1.1 U1.3 U3.1 U3.3 U4.7 U5.3 U10.6 | length 2632.4
  Top Layer w20: v1(1023,65) 1022.04,65.96 1022.04,140.52 C22.2@1019.56,143 1074.45,143 ; U1.1@1110.41,181.6 1110.41,178.96 1074.45,143 ; U1.3@1161.59,181.6 1159.87,179.88 1159.87,160.21 1142.67,143 1074.45,143 ; v1(2870,2270) 2870.96,2269.04 2870.96,2176.6 2888.44,2159.12 2996.21,2159.12 3025,2187.91 U5.3@3025,2212.52 ; U4.7@3607.48,2095 3582.87,2095 3554.08,2066.21 3554.08,2033.48 3584.59,2002.97 3594.49,2002.97 3625,1972.46 C10.1@3625,1931.42 3625.71,1930.71 3709.29,1930.71 v1(3710,1930) ; J6.1@3850,3987.5 3850,3760.55 4060.63,3549.92 C3.1@4060.63,3545 4062.11,3543.52 4062.11,3321.48 C6.1@4063.58,3320 ; U3.3@3874.41,3307.4 3876.13,3305.69 3876.13,3286.01 3885.5,3276.64 3914.5,3276.64 3923.87,3286.01 3923.87,3308.32 3927.72,3312.17 4055.75,3312.17 C6.1@4063.58,3320 ; C8.2@3920.08,3392.44 C8.2@3925,3392.44 3929.92,3392.44 4002.36,3320 C6.1@4063.58,3320 ; C21.1@4225,2383.58 4314.7,2383.58 4330,2368.28 ; U10.6@4238.75,2145 4261,2145 4330,2214 4330,2368.28 ; v1(4330,2425) 4330,2368.28 ; C23.1@4425,2383.58 4345.3,2383.58 4330,2368.28
-5: C1.1 C5.1 C18.1 C19.1 C20.1 C27.2 J7.1 J14.1 U4.4 U5.6 U10.4 U10.7 | length 2464.6
  Top Layer w20: v1(2875,1965) 2875,1966.35 2879.56,1970.91 C27.2@2879.56,2070 2938.27,2070 2949.15,2080.88 2996.21,2080.88 3025,2052.09 U5.6@3025,2027.48 ; C5.1@3100,3431.42 3101.48,3432.89 3110.33,3432.89 3125,3447.56 J7.1@3125,3987.5 3269.63,3842.87 3269.63,3696.15 3375,3590.78 C1.1@3375,3434.37 C1.1@3373.52,3432.89 ; C18.1@3750,2308.58 3758.86,2308.58 C18.1@3761.48,2305.96 ; U4.4@3792.52,2195 3792.52,2274.92 C18.1@3761.48,2305.96 ; v1(3845,2305) 3844.04,2305.96 C18.1@3761.48,2305.96 ; C20.1@4225,1931.42 4233.86,1931.42 4242.56,1940.12 4242.56,1980.12 4287.5,2025.06 4287.5,2068.5 ; U10.7@4238.75,2095 U10.7@4261,2095 ; v1(4300,1925) 4300.96,1925.96 4369.54,1925.96 C19.1@4375,1931.42 4375,1981 4287.5,2068.5 ; U10.4@4461.25,2195 4439,2195 4339,2095 U10.7@4261,2095 ; U10.7@4261,2095 4287.5,2068.5
ADA4940_IN_N: R26.1 R27.2 U5.1 | length 537.3
  Top Layer w15: R26.1@3048.39,2370 3140.55,2370 3311.57,2198.98 R27.2@3311.57,2195 3133.14,2195 3125,2203.14 U5.1@3125,2212.52
ADA4940_IN_P: R22.2 R25.1 U5.8 | length 384.8
  Top Layer w15: R25.1@3038.39,1870 3038.39,1873.94 3125,1960.55 U5.8@3125,2006.66 ; U5.8@3125,2027.48 U5.8@3125,2006.66 ; R22.2@3311.57,1995 3136.66,1995 U5.8@3125,2006.66
ADA4940_Vout+: J12.1 R26.2 U5.4 | length 335.5
  Top Layer w15: J12.1@2795,2370 R26.2@2971.61,2370 2975,2366.61 U5.4@2975,2212.52
ADA4940_Vout-: J9.3 R25.2 U5.5 | length 329.6
  Top Layer w15: J9.3@2795,1870 R25.2@2961.61,1870 2975,1883.39 U5.5@2975,2027.48
AGND: C2.2 C4.2 C11.1 C12.1 C13.1 C14.1 C15.1 C16.1 J4.1 J10.1 J13.2 J13.4 P5.1 P5.2 R18.1 R19.1 R20.1 R21.2 R23.2 R30.1 R31.2 TP5.1 U7.2 U8.2 U9.2 | length 1096.6
  Top Layer w6: R21.2@403.63,2840 R21.2@408.63,2845 ; C14.1@600,3267.44 C14.1@602.44,3265 ; C11.1@995,3412.44 C11.1@1000,3417.44 ; R31.2@1690,2841.37 R31.2@1693.63,2845
  Top Layer w10: U9.2@1825,3442 v1(1825,3525)
  Top Layer w20: v1(190,3810) 190.32,3809.69 259.69,3809.69 C2.2@260,3809.37 ; v1(225,3355) C13.1@225,3417.44 ; v1(320,2840) R21.2@403.63,2840 ; v1(400,3520) 400,3518.65 405,3513.65 U7.2@405,3442 ; C4.2@425,3806.42 427.63,3809.04 504.04,3809.04 v1(505,3810) ; C14.1@602.44,3265 v1(670,3265) ; v1(995,3355) C11.1@995,3412.44 ; v1(1110,2845) R23.2@1183.63,2845 ; U8.2@1200,3442 v1(1200,3515) ; v1(1400,3210) C12.1@1400,3267.44 ; v1(1650,3355) C15.1@1650,3417.44 ; v1(1690,2760) R31.2@1690,2841.37 ; v1(2045,3205) 2045,3262.44 C16.1@2050,3267.44 ; v1(2130,3365) 2198.5,3365 R18.1@2203.5,3370
  other v1: 1898.38,1927.12 1953.38,1927.12 2008.38,1927.12 2063.38,1927.12 2118.38,1927.12 2173.38,1927.12 1898.59,2022.88 1953.59,2022.88 2008.59,2022.88 2063.59,2022.88 2118.59,2022.88 2173.59,2022.88
Buffer_After_Filter_IN: P4.2 U4.3 | length 334.5
  Top Layer w15: U4.3@3792.52,2145 3818.11,2145 3900,2226.89 P4.2@3900,2420
CLK_BufferOut: P3.1 U2.9 | length 557.4
  Top Layer w10.7: U2.9@1280.7,551.1 1492.9,551.1 P3.1@1737,307
CLK_IN: J1.1 J13.5 J13.6 R1.1 U2.40 | length 3013.2
  Top Layer w10.7: R1.1@567.39,2279 570,2276.39 570,2170 ; J13.5@770,2170 J13.6@670,2170 570,2170 ; U2.40@991.3,551.1 391.9,551.1 175,768 J1.1@175,2170 570,2170
Code0: J13.12 U2.37 | length 1885.6
  Top Layer w10.7: J13.12@670,1870 501,1701 501,1158 501,1085.57 cw(c485.65,1085.57) 485.65,1070.21 476.32,1070.21 ccw(c476.32,1054.86) 460.97,1054.86 ccw(c476.32,1054.86) 476.32,1039.51 488.65,1039.51 cw(c488.65,1024.16) 504,1024.16 cw(c488.65,1024.16) 488.65,1008.81 466.35,1008.81 ccw(c466.35,993.46) 451,993.46 ccw(c466.35,993.46) 466.35,978.11 488.65,978.11 cw(c488.65,962.76) 504,962.76 cw(c488.65,962.76) 488.65,947.41 466.35,947.41 ccw(c466.35,932.05) 451,932.05 ccw(c466.35,932.05) 466.35,916.7 485.65,916.7 cw(c485.65,901.35) 501,901.35 501,896 501,862 752.46,610.54 990.92,610.54 U2.37@991.3,610.16
Code0_BufferOut: P3.3 U2.12 | length 1063.8
  Top Layer w10.7: U2.12@1280.7,610.16 1593.05,610.16 1636.1,567.1 1639.89,563.32 ccw(c1647.45,570.89) 1655.02,563.32 1661.35,569.64 cw(c1668.67,562.32) 1675.99,569.64 cw(c1668.67,562.32) 1675.99,555.01 1669.41,548.43 ccw(c1676.73,541.11) 1669.41,533.79 ccw(c1676.73,541.11) 1684.05,533.79 1690.62,540.37 cw(c1697.94,533.05) 1705.26,540.37 cw(c1697.94,533.05) 1705.26,525.73 1698.69,519.15 ccw(c1706.01,511.83) 1698.69,504.51 ccw(c1706.01,511.83) 1713.33,504.51 1719.9,511.09 cw(c1727.22,503.77) 1734.54,511.09 cw(c1727.22,503.77) 1734.54,496.45 1725.06,486.97 ccw(c1732.38,479.65) 1725.06,472.33 ccw(c1732.38,479.65) 1739.7,472.33 1749.18,481.81 cw(c1756.5,474.49) 1763.82,481.81 cw(c1756.5,474.49) 1763.82,467.17 1749.66,453.01 ccw(c1756.97,445.69) 1749.66,438.37 ccw(c1756.98,445.69) 1764.29,438.37 1778.46,452.53 cw(c1785.78,445.21) 1793.1,452.53 cw(c1785.78,445.21) 1793.1,437.9 1768.73,413.53 ccw(c1776.05,406.21) 1768.73,398.89 ccw(c1776.05,406.21) 1783.37,398.89 1786.27,401.79 cw(c1793.84,394.23) 1801.41,401.79 1823.82,379.39 1827.6,375.6 1890.43,312.77 1931.23,312.77 P3.3@1937,307
Code1: J13.14 U2.36 | length 1885.6
  Top Layer w10.7: J13.14@670,1770 567,1667 567,1345 567,1304.18 cw(c551.65,1304.18) 551.65,1288.83 ccw(c551.65,1273.48) 536.3,1273.48 ccw(c551.65,1273.48) 551.65,1258.13 cw(c551.65,1242.78) 567,1242.78 cw(c551.65,1242.78) 551.65,1227.43 541.31,1227.43 ccw(c541.31,1212.08) 525.96,1212.08 ccw(c541.31,1212.08) 541.31,1196.73 551.65,1196.73 cw(c551.65,1181.37) 567,1181.37 cw(c551.65,1181.37) 551.65,1166.02 536.05,1166.02 ccw(c536.05,1150.67) 520.7,1150.67 ccw(c536.05,1150.67) 536.05,1135.32 551.65,1135.32 cw(c551.65,1119.97) 567,1119.97 cw(c551.65,1119.97) 551.65,1104.62 536.05,1104.62 ccw(c536.05,1089.27) 520.7,1089.27 ccw(c536.05,1089.27) 536.05,1073.92 551.65,1073.92 cw(c551.65,1058.57) 567,1058.57 cw(c551.65,1058.57) 551.65,1043.21 536.05,1043.21 ccw(c536.05,1027.86) 520.7,1027.86 ccw(c536.05,1027.86) 536.05,1012.51 551.65,1012.51 cw(c551.65,997.16) 567,997.16 cw(c551.65,997.16) 551.65,981.81 536.05,981.81 ccw(c536.05,966.46) 520.7,966.46 ccw(c536.05,966.46) 536.05,951.11 551.65,951.11 cw(c551.65,935.76) 567,935.76 cw(c551.65,935.76) 551.65,920.41 540.27,920.41 ccw(c540.27,905.05) 524.92,905.05 ccw(c540.27,905.05) 540.27,889.7 551.65,889.7 cw(c551.65,874.35) 567,874.35 567,869 567,860.41 797.18,630.22 990.92,630.22 U2.36@991.3,629.84
Code1_BufferOut: P3.4 U2.13 | length 1067.4
  Top Layer w10.7: U2.13@1280.7,629.84 1714.16,629.84 1873.37,470.63 1877.15,466.85 ccw(c1884.72,474.41) 1892.29,466.84 1892.63,467.18 cw(c1899.94,459.86) 1907.26,467.18 cw(c1899.94,459.86) 1907.26,452.54 1879.48,424.75 ccw(c1886.8,417.43) 1879.48,410.11 ccw(c1886.8,417.43) 1894.11,410.11 1921.9,437.9 cw(c1929.22,430.58) 1936.54,437.9 cw(c1929.22,430.58) 1936.54,423.26 1915.09,401.81 ccw(c1922.41,394.49) 1915.09,387.17 ccw(c1922.41,394.49) 1929.73,387.17 1935.71,393.15 cw(c1943.28,385.59) 1950.85,393.15 1984.59,359.41 1988.37,355.63 P3.4@2037,307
